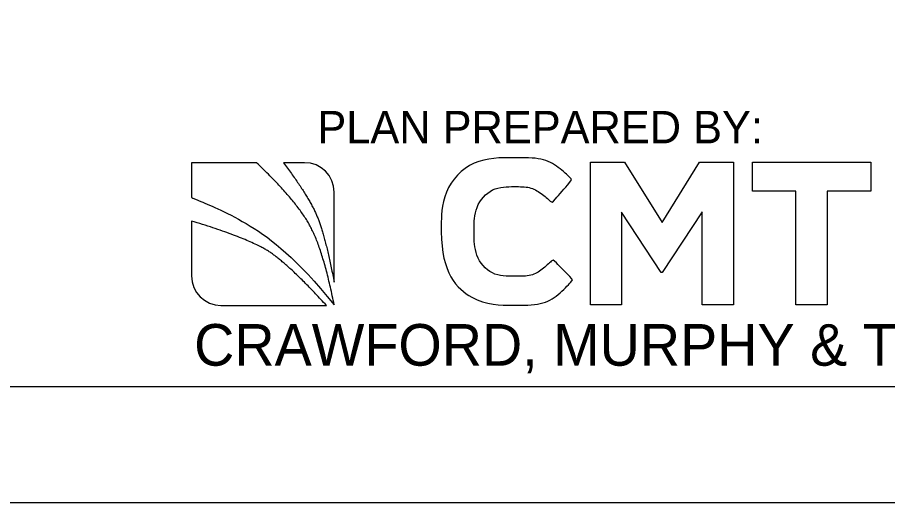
# Model space of a CAD drawing. Extents: x 0 to 42, y 0 to 22.
# Drawn here: x 2.317 to 6.076, y 0 to 2.097 of the extents above; entities that cross this region are included whole.
import ezdxf

# ---------------------------------------------------------------- set-up
doc = ezdxf.new("R2010")
doc.units = 0
for name, color, linetype in [('GM_X_Adjacent_County', 7, 'Continuous'), ('GM_X_Adjacent_County_Text', 7, 'Continuous'), ('GM_X_County', 7, 'Continuous'), ('GM_X_Minor_Lake', 7, 'Continuous'), ('GM_X_Section', 7, 'Continuous')]:
    doc.layers.add(name, color=color, linetype=linetype)

msp = doc.modelspace()

# ---------------------------------------------------------------- linework, layer by layer
at = {"layer": 'GM_X_Adjacent_County_Text'}
for p, q in [((4.7929, 1.4717), (4.9392, 1.4717)), ((4.7929, 0.8549), (4.7929, 1.4717)), ((4.9392, 1.4717), (5.1013, 1.2109)), ((5.1013, 1.2109), (5.2634, 1.4717)), ((5.2634, 1.4717), (5.4097, 1.4717)), ((5.4097, 1.4717), (5.4097, 0.8549)), ((5.4919, 1.3466), (5.4919, 1.4717)), ((5.4919, 1.4717), (6.0029, 1.4717)), ((6.0029, 1.4717), (6.0029, 1.3466)), ((5.6796, 1.3466), (5.4919, 1.3466)), ((5.6796, 0.8549), (5.6796, 1.3466)), ((6.0029, 1.3466), (5.8152, 1.3466)), ((5.8152, 1.3466), (5.8152, 0.8549)), ((5.0978, 0.9941), (4.926, 1.2549)), ((4.926, 1.2549), (4.926, 0.8549)), ((5.2749, 1.2576), (5.1013, 0.9941)), ((5.2749, 0.8549), (5.2749, 1.2576)), ((5.1013, 0.9941), (5.0978, 0.9941)), ((4.926, 0.8549), (4.7929, 0.8549)), ((5.4097, 0.8549), (5.2749, 0.8549)), ((5.8152, 0.8549), (5.6796, 0.8549))]:
    msp.add_line(p, q, dxfattribs=at)
msp.add_open_spline([(4.1479, 1.1702), (4.1479, 1.1702), (4.1479, 1.1719), (4.1479, 1.1719), (4.1479, 1.3473), (4.2801, 1.4909), (4.4695, 1.4909), (4.5858, 1.4909), (4.6554, 1.4521), (4.7127, 1.3957), (4.7127, 1.3957), (4.6263, 1.2962), (4.6263, 1.2962), (4.5788, 1.3393), (4.5303, 1.3658), (4.4686, 1.3658), (4.3647, 1.3658), (4.2898, 1.2794), (4.2898, 1.1737), (4.2898, 1.1737), (4.2898, 1.1719), (4.2898, 1.1719), (4.2898, 1.0662), (4.3629, 0.9781), (4.4686, 0.9781), (4.5391, 0.9781), (4.5823, 1.0063), (4.6307, 1.0503), (4.6307, 1.0503), (4.7171, 0.9631), (4.7171, 0.9631), (4.6536, 0.8953), (4.5832, 0.853), (4.4642, 0.853), (4.2827, 0.853), (4.1479, 0.9931), (4.1479, 1.1702)], degree=3, dxfattribs=at)
at = {"layer": 'GM_X_County'}
msp.add_lwpolyline([(1.5, 21.5), (33.5, 21.5), (33.5, 0.5), (1.5, 0.5)], close=True, dxfattribs=at)
at = {"layer": 'GM_X_Minor_Lake'}
for p, q in [((3.3494, 1.4693), (3.0687, 1.4693)), ((3.0687, 1.4693), (3.0687, 1.3186)), ((3.5575, 1.4693), (3.4658, 1.4693)), ((3.6849, 0.9528), (3.6849, 1.342)), ((3.0687, 1.217), (3.0687, 0.98)), ((3.1961, 0.8526), (3.6516, 0.8526)), ((3.6849, 0.8547), (3.6849, 0.8549))]:
    msp.add_line(p, q, dxfattribs=at)
msp.add_lwpolyline([(3.6516, 0.8526), (3.6516, 0.8526)], dxfattribs=at)
for centre, start, end in [((3.5575, 1.342), 360, 90), ((3.1961, 0.98), 180, 270)]:
    msp.add_arc(centre, 0.1274, start, end, dxfattribs=at)
for points, degree in [([(3.6849, 0.8549), (3.6383, 1.0929), (3.518, 1.3092), (3.3494, 1.4693)], 2), ([(3.4658, 1.4693), (3.578, 1.321), (3.6487, 1.1435), (3.6849, 0.9528)], 2), ([(3.0687, 1.3186), (3.0689, 1.3185), (3.069, 1.3185), (3.0691, 1.3184), (3.3096, 1.219), (3.5207, 1.0583), (3.6849, 0.8547)], 3), ([(3.6516, 0.8526), (3.4999, 1.0178), (3.3267, 1.1392), (3.0687, 1.217)], 2)]:
    msp.add_open_spline(points, degree=degree, dxfattribs=at)
at = {"layer": 'GM_X_Section'}
msp.add_lwpolyline([(0, 0), (34, 0), (34, 22), (0, 22)], close=True, dxfattribs=at)

# ---------------------------------------------------------------- texts
at = {"layer": 'GM_X_Adjacent_County'}
msp.add_text('PLAN PREPARED BY:', height=0.14, dxfattribs=at).set_placement((3.6125, 1.553))
at = {"layer": 'GM_X_Adjacent_County_Text'}
msp.add_text('CRAWFORD, MURPHY & TILLY, INC.', height=0.18, dxfattribs=at).set_placement((3.0801, 0.5918))

doc.saveas('drawing.dxf')
